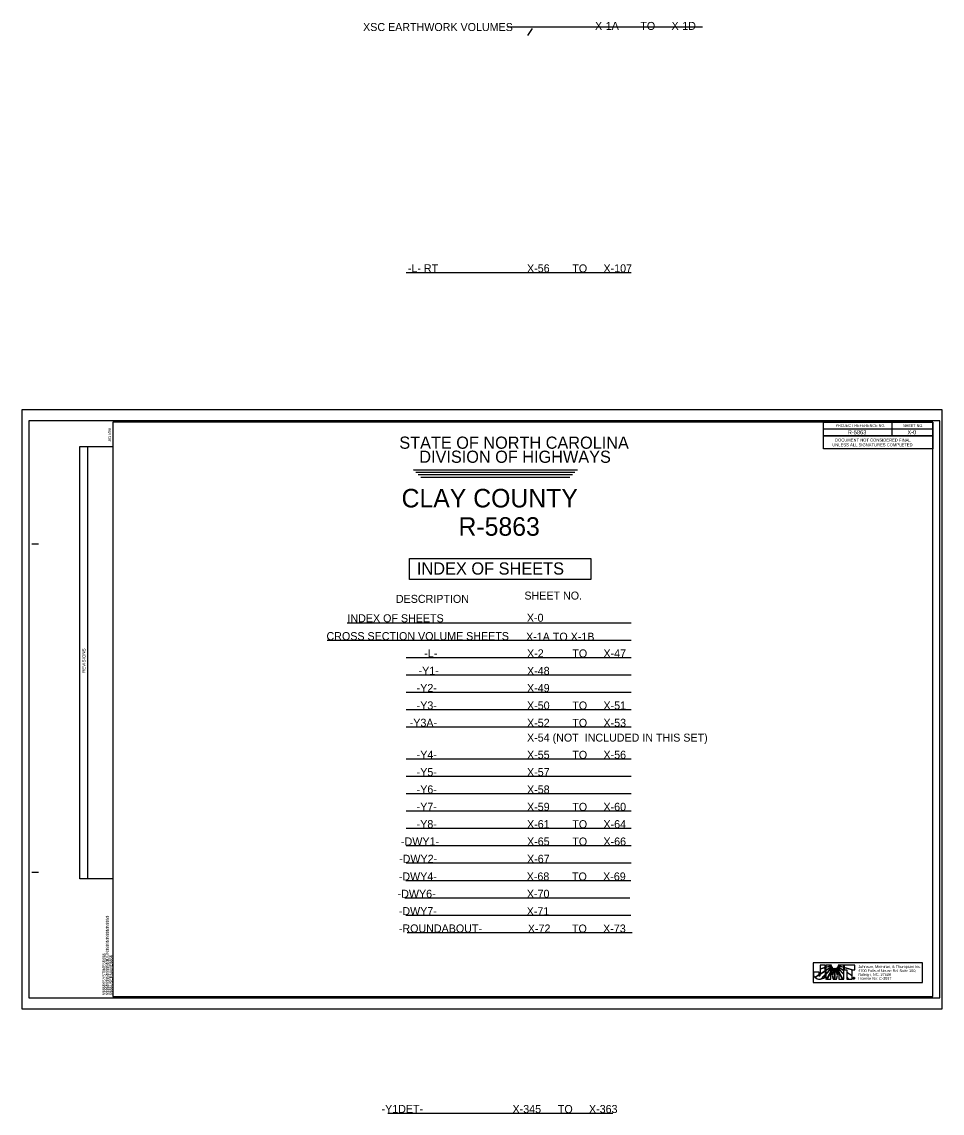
# Model space of a CAD drawing. Extents: x -1147 to 1810, y 2549 to 4545.
# Drawn here: x -1147 to 536, y 2549 to 4545 of the extents above; entities that cross this region are included whole.
import ezdxf

# ---------------------------------------------------------------- set-up
doc = ezdxf.new("R2010")
doc.units = 0
for name, color, linetype in [('Default', 7, 'Continuous'), ('Old_Level_12', 7, 'Continuous'), ('Old_Level_40', 7, 'Continuous'), ('Old_Level_44', 7, 'Continuous'), ('Prop Dimension Text', 7, 'Continuous'), ('Scratch_Level_1', 7, 'Continuous'), ('Sheet Block Revision CELL', 7, 'Continuous'), ('Sheet Cutting Line CELL', 7, 'Continuous'), ('Sheet Data Field CELL', 7, 'Continuous'), ('Sheet Plan CELL', 7, 'Continuous'), ('Sheet Plot Border Inside CELL', 7, 'Continuous'), ('Sheet Plot Border Outside CELL', 7, 'Continuous'), ('Sheet Sticker Exception Certification CELL', 7, 'Continuous')]:
    doc.layers.add(name, color=color, linetype=linetype)

msp = doc.modelspace()

# ---------------------------------------------------------------- linework, layer by layer
at = {"layer": 'Default'}
msp.add_lwpolyline([(-438.3, 3563.7), (-106.5, 3563.7), (-106.5, 3525), (-438.3, 3525)], close=True, dxfattribs=at)
at = {"layer": 'Old_Level_12'}
for p, q in [((-431.1, 3725.9), (-131, 3725.8)), ((-431.1, 3725.8), (-131, 3725.8)), ((-426.8, 3721.2), (-135.6, 3721.2)), ((-422.2, 3716.7), (-140.1, 3716.7)), ((-417.7, 3712.3), (-144.7, 3712.3))]:
    msp.add_line(p, q, dxfattribs=at)
at = {"layer": 'Prop Dimension Text'}
for p, q in [((322.3, 2819.6), (312.9, 2819.6)), ((312.9, 2819.6), (313, 2813.4)), ((313, 2813.4), (322.3, 2816)), ((322.3, 2815.3), (313, 2812.6)), ((322.3, 2816), (322.3, 2819.6)), ((322.3, 2809.9), (322.3, 2815.3)), ((333.8, 2819.6), (323.3, 2819.6)), ((323.3, 2819.6), (323.3, 2816.3)), ((323.3, 2816.3), (331.1, 2818.4)), ((331.1, 2817.7), (323.3, 2815.5)), ((323.3, 2815.5), (323.3, 2810.5)), ((323.3, 2810.5), (330.3, 2814.9)), ((331.4, 2814.8), (323.3, 2809.7)), ((323.3, 2803.8), (333.2, 2814.1)), ((333.6, 2813.6), (323.3, 2802.8)), ((330.3, 2814.9), (334.2, 2818.1)), ((331.1, 2818.4), (333.8, 2819.6)), ((334.2, 2818.1), (331.1, 2817.7)), ((335, 2816.6), (331.4, 2814.8)), ((333.2, 2814.1), (335, 2816.6)), ((336, 2815.5), (333.6, 2813.6)), ((334.9, 2812.5), (336, 2815.5)), ((337.4, 2814.7), (335.5, 2812.3)), ((337.1, 2811.8), (337.4, 2814.7)), ((338.9, 2814.3), (337.7, 2811.3)), ((339.3, 2806.9), (338.9, 2814.3)), ((340.5, 2814.3), (340, 2806.9)), ((341.7, 2811.3), (340.5, 2814.3)), ((342, 2814.7), (342.3, 2811.7)), ((343.8, 2812.3), (342, 2814.7)), ((343.3, 2815.5), (344.5, 2812.5)), ((345.8, 2813.6), (343.3, 2815.5)), ((344.4, 2816.6), (346.2, 2814.1)), ((348, 2814.8), (344.4, 2816.6)), ((345.2, 2818.1), (349.1, 2814.9)), ((348.1, 2817.7), (345.2, 2818.1)), ((356.1, 2819.6), (345.7, 2819.6)), ((345.7, 2819.6), (348.4, 2818.4)), ((356.1, 2802.8), (345.8, 2813.6)), ((346.2, 2814.1), (356.1, 2803.7)), ((356.1, 2809.7), (348, 2814.8)), ((356.1, 2815.5), (348.1, 2817.7)), ((348.4, 2818.4), (356.1, 2816.2)), ((349.1, 2814.9), (356.1, 2810.6)), ((356.1, 2816.2), (356.1, 2819.6)), ((356.1, 2810.6), (356.1, 2815.5)), ((376.5, 2819.7), (356.8, 2819.7)), ((356.8, 2819.7), (356.9, 2816)), ((356.9, 2816), (356.9, 2815.9)), ((356.9, 2815.9), (372.4, 2811.6)), ((356.9, 2815.4), (356.9, 2815.3)), ((371.4, 2811.2), (356.9, 2815.4)), ((356.9, 2815.3), (356.9, 2811.5)), ((376.5, 2811.6), (376.5, 2819.7)), ((313, 2812.6), (313, 2803.9)), ((313, 2803.9), (322.3, 2809.9)), ((323.3, 2809.7), (323.3, 2803.8)), ((323.3, 2802.8), (323.3, 2794.3)), ((323.3, 2794.3), (324.8, 2794.3)), ((324.8, 2794.3), (332.5, 2808.2)), ((332.5, 2806.8), (325.6, 2794.3)), ((325.6, 2794.3), (332.6, 2794.3)), ((332.5, 2808.2), (332.5, 2810.6)), ((332.5, 2810.6), (332.9, 2808.9)), ((332.6, 2794.3), (332.5, 2806.8)), ((332.9, 2808.9), (334.9, 2812.5)), ((335.5, 2812.3), (333.2, 2808.1)), ((333.2, 2808.1), (334.7, 2802.4)), ((334.7, 2802.4), (337.1, 2811.8)), ((337.7, 2811.3), (335, 2801.1)), ((335, 2801.1), (336.8, 2794.4)), ((336.8, 2794.4), (339.4, 2794.4)), ((339.4, 2794.4), (339.3, 2806.9)), ((340, 2806.9), (340, 2794.4)), ((340, 2794.4), (342.6, 2794.4)), ((344.4, 2801), (341.7, 2811.3)), ((342.3, 2811.7), (344.7, 2802.2)), ((342.6, 2794.4), (344.4, 2801)), ((346.2, 2807.9), (343.8, 2812.3)), ((344.5, 2812.5), (346.5, 2808.8)), ((344.7, 2802.2), (346.2, 2807.9)), ((346.5, 2808.8), (346.9, 2810.7)), ((346.9, 2810.7), (346.9, 2807.9)), ((346.9, 2807.9), (354.4, 2794.4)), ((353.7, 2794.4), (346.9, 2806.6)), ((346.9, 2806.6), (347, 2794.4)), ((347, 2794.4), (353.7, 2794.4)), ((354.4, 2794.4), (356.1, 2794.4)), ((356.1, 2803.7), (356.1, 2809.7)), ((356.1, 2794.4), (356.1, 2802.8)), ((356.9, 2811.5), (361.7, 2811.5)), ((361.7, 2811.5), (361.7, 2807.1)), ((361.7, 2807.1), (371.4, 2800.9)), ((361.7, 2806.3), (361.7, 2797.9)), ((371.4, 2800.2), (361.7, 2806.3)), ((361.7, 2797.9), (365, 2794.4)), ((364.1, 2794.4), (361.7, 2797)), ((361.7, 2797), (361.7, 2794.4)), ((361.7, 2794.4), (364.1, 2794.4)), ((365, 2794.4), (371.4, 2794.4)), ((371.4, 2800.9), (371.4, 2811.2)), ((371.4, 2794.4), (371.4, 2800.2)), ((372.4, 2811.6), (376.5, 2811.6)), ((373.8, 2795.3), (373.8, 2796.7)), ((373.8, 2796.7), (374.4, 2796.7)), ((374.2, 2795.3), (373.8, 2795.3)), ((374.4, 2796.4), (374.2, 2796.4)), ((374.2, 2796.4), (374.2, 2796.1)), ((374.2, 2796.1), (374.4, 2796.1)), ((374.4, 2795.8), (374.2, 2795.8)), ((374.2, 2795.8), (374.2, 2795.3)), ((374.4, 2797.5), (374.4, 2797.2)), ((374.4, 2797.2), (374.4, 2797.5)), ((374.4, 2796.7), (374.4, 2796.4)), ((374.4, 2796.4), (374.4, 2796.7)), ((374.4, 2796.7), (374.5, 2796.7)), ((374.5, 2796.4), (374.4, 2796.4)), ((374.4, 2796.1), (374.4, 2795.8)), ((374.4, 2795.8), (374.4, 2796.1)), ((374.4, 2796.1), (374.4, 2796.1)), ((374.4, 2795.8), (374.4, 2795.8)), ((374.4, 2794.7), (374.4, 2794.4)), ((374.4, 2794.4), (374.4, 2794.7)), ((374.4, 2794.7), (374.4, 2794.7)), ((374.4, 2794.4), (374.4, 2794.4))]:
    msp.add_line(p, q, dxfattribs=at)
msp.add_lwpolyline([(300.3, 2787.9), (500.3, 2787.9), (500.3, 2824), (300.3, 2824)], close=True, dxfattribs=at)
for points in [[(313, 2813.4), (322.3, 2816), (322.3, 2819.6), (312.9, 2819.6), (313, 2813.4)], [(313, 2803.9), (322.3, 2809.9), (322.3, 2815.3), (313, 2812.6), (313, 2803.9)], [(331.1, 2818.4), (333.8, 2819.6), (323.3, 2819.6), (323.3, 2816.3), (331.1, 2818.4)], [(323.3, 2815.5), (323.3, 2810.5), (330.3, 2814.9), (334.2, 2818.1), (331.1, 2817.7), (323.3, 2815.5)], [(323.3, 2809.7), (323.3, 2803.8), (333.2, 2814.1), (335, 2816.6), (331.4, 2814.8), (323.3, 2809.7)], [(336, 2815.5), (333.6, 2813.6), (323.3, 2802.8), (323.3, 2794.3), (324.8, 2794.3), (332.5, 2808.2), (332.5, 2810.6), (332.9, 2808.9), (334.9, 2812.5), (336, 2815.5)], [(337.4, 2814.7), (335.5, 2812.3), (333.2, 2808.1), (334.7, 2802.4), (337.1, 2811.8), (337.4, 2814.7)], [(337.7, 2811.3), (335, 2801.1), (336.8, 2794.4), (339.4, 2794.4), (339.3, 2806.9), (338.9, 2814.3), (337.7, 2811.3)], [(340.5, 2814.3), (340, 2806.9), (340, 2794.4), (342.6, 2794.4), (344.4, 2801), (341.7, 2811.3), (340.5, 2814.3)], [(342, 2814.7), (342.3, 2811.7), (344.7, 2802.2), (346.2, 2807.9), (343.8, 2812.3), (342, 2814.7)], [(343.3, 2815.5), (344.5, 2812.5), (346.5, 2808.8), (346.9, 2810.7), (346.9, 2807.9), (354.4, 2794.4), (356.1, 2794.4), (356.1, 2802.8), (345.8, 2813.6), (343.3, 2815.5)], [(344.4, 2816.6), (346.2, 2814.1), (356.1, 2803.7), (356.1, 2809.7), (348, 2814.8), (344.4, 2816.6)], [(345.2, 2818.1), (349.1, 2814.9), (356.1, 2810.6), (356.1, 2815.5), (348.1, 2817.7), (345.2, 2818.1)], [(348.4, 2818.4), (356.1, 2816.2), (356.1, 2819.6), (345.7, 2819.6), (348.4, 2818.4)], [(376.5, 2819.7), (356.8, 2819.7), (356.9, 2816), (356.9, 2815.9), (372.4, 2811.6), (376.5, 2811.6), (376.5, 2819.7)], [(356.9, 2815.4), (356.9, 2815.3), (356.9, 2811.5), (361.7, 2811.5), (361.7, 2807.1), (371.4, 2800.9), (371.4, 2811.2), (356.9, 2815.4)], [(325.6, 2794.3), (332.6, 2794.3), (332.5, 2806.8), (325.6, 2794.3)], [(347, 2794.4), (353.7, 2794.4), (346.9, 2806.6), (347, 2794.4)], [(361.7, 2806.3), (361.7, 2797.9), (365, 2794.4), (371.4, 2794.4), (371.4, 2800.2), (361.7, 2806.3), (361.7, 2806.3)], [(361.7, 2794.4), (361.7, 2794.4), (364.1, 2794.4), (361.7, 2797), (361.7, 2794.4)], [(375.1, 2795.6), (375.1, 2795.5), (375.1, 2795.5), (375.1, 2795.4), (375.1, 2795.3), (374.8, 2795.3)]]:
    msp.add_lwpolyline(points, dxfattribs=at)
for points, degree in [([(310.3, 2807.9), (310.3, 2807.9), (301.6, 2807.9), (301.6, 2807.9), (301.6, 2807.9), (301.6, 2802.5), (301.6, 2802.5), (301.6, 2802.5), (301.6, 2801.9), (301.6, 2801.9), (301.6, 2800.2), (302.2, 2798.9), (303.2, 2797.8), (303.2, 2797.8), (310.3, 2802.1), (310.3, 2802.2), (310.3, 2802.2), (310.3, 2807.9), (310.3, 2807.9)], 3), ([(311.6, 2800.1), (311.1, 2800.1), (310.6, 2800.4), (310.4, 2801.5), (310.4, 2801.5), (303.7, 2797.3), (303.7, 2797.3), (305.7, 2795.1), (309, 2793.8), (311.8, 2793.8), (312.6, 2793.8), (313.1, 2793.9), (313.9, 2794.1), (313.9, 2794.1), (322.3, 2802.8), (322.3, 2802.8), (322.3, 2802.8), (322.3, 2809.1), (322.3, 2809.1), (322.3, 2809.1), (313, 2803.1), (313, 2803.1), (313, 2800.8), (312.4, 2800.1), (311.6, 2800.1)], 3), ([(311.6, 2800.1), (311.1, 2800.1), (310.6, 2800.4), (310.4, 2801.5), (310.4, 2801.5), (303.7, 2797.3), (303.7, 2797.3), (305.7, 2795.1), (309, 2793.8), (311.8, 2793.8), (312.6, 2793.8), (313.1, 2793.9), (313.9, 2794.1), (313.9, 2794.1), (322.3, 2802.8), (322.3, 2802.8), (322.3, 2802.8), (322.3, 2809.1), (322.3, 2809.1), (322.3, 2809.1), (313, 2803.1), (313, 2803.1), (313, 2800.8), (312.4, 2800.1), (311.6, 2800.1)], 3), ([(322.3, 2801.8), (322.3, 2801.8), (315, 2794.3), (315, 2794.3), (318.6, 2795.1), (322.2, 2797.5), (322.3, 2801.8)], 3), ([(374.4, 2794.4), (374, 2794.4), (373.6, 2794.5), (373.3, 2794.9), (373, 2795.2), (372.8, 2795.5), (372.8, 2796), (372.8, 2796.4), (373, 2796.8), (373.3, 2797.1), (373.6, 2797.4), (374, 2797.5), (374.4, 2797.5)], 3), ([(374.4, 2797.2), (374.1, 2797.2), (373.8, 2797.1), (373.5, 2796.9), (373.3, 2796.6), (373.2, 2796.3), (373.2, 2796), (373.2, 2795.6), (373.3, 2795.3), (373.5, 2795.1), (373.8, 2794.8), (374.1, 2794.7), (374.4, 2794.7)], 3), ([(374.4, 2797.5), (374.9, 2797.5), (375.2, 2797.4), (375.6, 2797.1), (375.9, 2796.8), (376, 2796.4), (376, 2796)], 3), ([(374.4, 2794.7), (374.8, 2794.7), (375.1, 2794.8), (375.3, 2795.1), (375.6, 2795.3), (375.7, 2795.6), (375.7, 2796), (375.7, 2796.3), (375.6, 2796.6), (375.3, 2796.9), (375.1, 2797.1), (374.8, 2797.2), (374.4, 2797.2)], 3), ([(374.4, 2796.1), (374.6, 2796.1), (374.8, 2796.1), (374.8, 2796.3), (374.8, 2796.4), (374.7, 2796.4), (374.5, 2796.4)], 3), ([(376, 2796), (376, 2795.5), (375.9, 2795.2), (375.6, 2794.8), (375.3, 2794.5), (374.9, 2794.4), (374.4, 2794.4)], 3), ([(374.7, 2795.8), (374.6, 2795.8), (374.6, 2795.8), (374.4, 2795.8)], 2), ([(374.5, 2796.7), (374.9, 2796.7), (375.1, 2796.6), (375.1, 2796.3), (375.1, 2796.1), (375, 2796), (374.9, 2796)], 3), ([(374.8, 2795.3), (374.8, 2795.3), (374.7, 2795.4), (374.7, 2795.5), (374.7, 2795.7), (374.7, 2795.7), (374.7, 2795.8)], 3), ([(374.9, 2796), (375, 2795.9), (375, 2795.8), (375.1, 2795.6)], 2)]:
    msp.add_open_spline(points, degree=degree, dxfattribs=at)
at = {"layer": 'Scratch_Level_1'}
for p, q in [((-259, 4535.2), (-220.9, 4535.2)), ((-259, 4535.2), (97.9, 4535.2)), ((-222, 4519.9), (-213.3, 4532.3)), ((-444.1, 4086.5), (-32.7, 4086.5)), ((-552.1, 3445.8), (-32.7, 3445.8)), ((-588.7, 3414.1), (-32.7, 3414.1)), ((-444.1, 3382.4), (-32.7, 3382.4)), ((-444.1, 3350.7), (-32.7, 3350.7)), ((-444.1, 3319), (-32.7, 3319)), ((-444.1, 3287.3), (-32.7, 3287.3)), ((-444.1, 3255.6), (-32.7, 3255.6)), ((-444.1, 3197.1), (-32.7, 3197.1)), ((-444.1, 3165.4), (-32.7, 3165.4)), ((-444.1, 3133.7), (-32.7, 3133.7)), ((-444.1, 3102), (-32.7, 3102)), ((-444.1, 3070.3), (-32.7, 3070.3)), ((-444.1, 3038.6), (-32.7, 3038.6)), ((-444.1, 3006.9), (-32.7, 3006.9)), ((-444.7, 2974.6), (-33.3, 2974.6)), ((-446.8, 2942.9), (-35.3, 2942.9)), ((-444.7, 2911.2), (-33.3, 2911.2)), ((-442.6, 2879.5), (-31.2, 2879.5)), ((-477.7, 2549.4), (-66.2, 2549.4))]:
    msp.add_line(p, q, dxfattribs=at)
at = {"layer": 'Sheet Block Revision CELL'}
msp.add_line((-1026.8, 2977.7), (-1026.8, 3768.4), dxfattribs=at)
msp.add_lwpolyline([(-1041.4, 2977.7), (-1041.4, 3768.3), (-980.8, 3768.4), (-980.8, 2977.7)], close=True, dxfattribs=at)
at = {"layer": 'Sheet Cutting Line CELL'}
for p, q in [((536.2, 3835.2), (-1147.3, 3835.2)), ((-1147.3, 3835.2), (-1147.3, 2740.2)), ((-1147.3, 2740.2), (536.2, 2740.2))]:
    msp.add_line(p, q, dxfattribs=at)
at = {"layer": 'Sheet Plan CELL'}
for p, q in [((-980.8, 3812.7), (-980.8, 3812.7)), ((444.1, 3812.7), (444.2, 3787.7)), ((319.1, 3800.2), (519.2, 3800.2)), ((319.1, 3787.6), (519.2, 3787.7)), ((319.1, 3787.6), (519.2, 3787.7)), ((-1129.3, 3590.2), (-1116.8, 3590.2)), ((-1129.3, 2990.2), (-1116.8, 2990.2)), ((-980.8, 2762.7), (-980.8, 2762.7))]:
    msp.add_line(p, q, dxfattribs=at)
for points in [[(519.2, 3812.7), (-980.8, 3812.7), (-980.8, 2762.7), (519.2, 2762.7)], [(319.1, 3812.7), (519.2, 3812.7), (519.2, 3787.7), (319.1, 3787.6)]]:
    msp.add_lwpolyline(points, close=True, dxfattribs=at)
at = {"layer": 'Sheet Plot Border Inside CELL'}
msp.add_lwpolyline([(-1134.3, 2760.2), (531.7, 2760.2), (531.7, 3815.2), (-1134.3, 3815.2)], close=True, dxfattribs=at)
at = {"layer": 'Sheet Plot Border Outside CELL'}
msp.add_lwpolyline([(-1147.3, 2740.2), (536.2, 2740.2), (536.2, 3835.2), (-1147.3, 3835.2)], close=True, dxfattribs=at)
at = {"layer": 'Sheet Sticker Exception Certification CELL'}
for p, q in [((319.1, 3764.1), (319.1, 3787.6)), ((319.1, 3787.6), (519.2, 3787.6)), ((519.2, 3787.6), (519.2, 3764.1)), ((519.2, 3764.1), (319.1, 3764.1))]:
    msp.add_line(p, q, dxfattribs=at)

# ---------------------------------------------------------------- texts
at = {"layer": 'Default'}
for s, p in [('XSC EARTHWORK VOLUMES ', (-523.1, 4527.8)), ('X-1A', (-98.8, 4529.9)), ('TO', (-15.9, 4529.8)), ('X-1D', (41.1, 4529.9)), ('-L- RT', (-441.2, 4086.7)), ('X-56', (-223.2, 4086.6)), ('TO', (-140.4, 4086.5)), ('X-107', (-83.4, 4086.6)), ('INDEX OF SHEETS ', (-551.7, 3446.8)), ('X-0', (-223.5, 3447.7)), ('CROSS SECTION VOLUME SHEETS', (-590, 3414.2)), ('X-1A TO X-1B', (-224.9, 3413.2)), ('-L- ', (-411.2, 3382.8)), ('X-2', (-223.2, 3382.7)), ('TO', (-140.4, 3382.6)), ('X-47', (-83.4, 3382.7)), ('-Y1-', (-421.6, 3350.8)), ('X-48', (-223.2, 3350.7)), ('-Y2- ', (-425.1, 3319.3)), ('X-49', (-223.2, 3319.3)), ('-Y3-', (-425.1, 3287.5)), ('X-50', (-223.2, 3287.4)), ('TO', (-140.4, 3287.3)), ('X-51', (-83.4, 3287.4)), ('-Y3A-', (-437.8, 3255.8)), ('X-52', (-223.2, 3255.7)), ('TO', (-140.4, 3255.6)), ('X-53', (-83.4, 3255.7)), ('X-54 (NOT  INCLUDED IN THIS SET)', (-223.2, 3228.6)), ('-Y4-', (-425.1, 3197.3)), ('X-55', (-223.2, 3197.3)), ('TO', (-140.4, 3197.2)), ('X-56', (-83.4, 3197.3)), ('-Y5-', (-425.1, 3165.6)), ('X-57', (-223.2, 3165.6)), ('-Y6-', (-425.1, 3133.9)), ('X-58', (-223.2, 3133.8)), ('-Y7-', (-425.1, 3102.2)), ('X-59', (-223.2, 3102.1)), ('TO', (-140.4, 3102)), ('X-60', (-83.4, 3102.1)), ('-Y8-', (-425.1, 3070.5)), ('X-61', (-223.2, 3070.4)), ('TO', (-140.4, 3070.3)), ('X-64', (-83.4, 3070.4)), ('-DWY1-', (-453.7, 3038.8)), ('X-65', (-223.2, 3038.7)), ('TO', (-140.4, 3038.6)), ('X-66', (-83.4, 3038.7)), ('-DWY2-', (-457.2, 3007.1)), ('X-67', (-223.2, 3007)), ('-DWY4-', (-457.8, 2974.8)), ('X-68', (-223.8, 2974.8)), ('TO', (-141, 2974.7)), ('X-69', (-84, 2974.8)), ('-DWY6-', (-459.9, 2943.1)), ('X-70', (-223.5, 2943.1)), ('-DWY7-', (-457.8, 2911.4)), ('X-71', (-223.8, 2911.3)), ('-ROUNDABOUT-', (-457.7, 2879.7)), ('X-72', (-221.7, 2879.6)), ('TO', (-141, 2879.5)), ('X-73', (-84, 2879.6)), ('-Y1DET-', (-489.3, 2549.7)), ('X-345', (-249.7, 2549.6)), ('TO', (-166.8, 2549.5)), ('X-363', (-109.9, 2549.6))]:
    msp.add_text(s, height=14.63, dxfattribs=at).set_placement(p)
for s, height, p in [('INDEX OF SHEETS', 22.358, (-424.7, 3534)), ('DESCRIPTION', 14.63, (-463.1, 3482.3)), ('SHEET NO.', 14.63, (-228, 3488.3))]:
    msp.add_text(s, height=height, rotation=359.992, dxfattribs=at).set_placement(p)
at = {"layer": 'Old_Level_40'}
for s, height, p in [('CLAY COUNTY', 33.906, (-452.7, 3656.8)), ('R-5863', 33.91, (-348.6, 3605))]:
    msp.add_text(s, height=height, rotation=359.9982, dxfattribs=at).set_placement(p)
at = {"layer": 'Old_Level_44'}
for s, p in [('STATE OF NORTH CAROLINA', (-456.8, 3764.1)), ('DIVISION OF HIGHWAYS', (-420.3, 3738.4))]:
    msp.add_text(s, height=22.246, rotation=359.9915, dxfattribs=at).set_placement(p)
at = {"layer": 'Prop Dimension Text'}
for s, height, p in [('Johnson, Mirmiran, & Thompson Inc.', 5.111, (382.7, 2814.7)), ('4700 Falls of Neuse Rd, Suite 100, ', 4.965, (382.7, 2807.2)), ('Raleigh, NC, 27609', 4.965, (382.7, 2800.2)), ('License No: C-3097', 4.965, (382.7, 2793.1))]:
    msp.add_text(s, height=height, dxfattribs=at).set_placement(p)
msp.add_text('www.jmt.com', height=1.241, rotation=270, dxfattribs=at).set_placement((340.6, 2805.6))
at = {"layer": 'Sheet Block Revision CELL'}
msp.add_text('REVISIONS', height=6, rotation=90, dxfattribs=at).set_placement((-1030.9, 3353.9))
at = {"layer": 'Sheet Data Field CELL'}
for s, p in [('R-5863', (363.5, 3790.4)), ('X-0', (472.6, 3790.5))]:
    msp.add_text(s, height=7.5, rotation=0, dxfattribs=at).set_placement(p)
at = {"layer": 'Sheet Plan CELL'}
for s, height, rotation, p in [('8/17/99', 5.25, 90, (-984.1, 3777.5)), ('PROJECT REFERENCE NO.', 5, 0, (341.3, 3804)), ('SHEET NO.', 5, 0, (464.5, 3803.9)), ('$$$$$$$$$$$$$$$$DGN$$$$$$$$$$$$$$$$', 5.25, 90, (-988.5, 2765.1)), ('$$$$$$SYSTIME$$$$$', 5.25, 90, (-994.6, 2765.1)), ('$$$$USERNAME$$$$', 5.25, 90, (-981.9, 2765.1))]:
    msp.add_text(s, height=height, rotation=rotation, dxfattribs=at).set_placement(p)
at = {"layer": 'Sheet Sticker Exception Certification CELL'}
for s, p in [('UNLESS ALL SIGNATURES COMPLETED', (335.1, 3768.5)), ('DOCUMENT NOT CONSIDERED FINAL', (340.2, 3777.3))]:
    msp.add_text(s, height=5.5, dxfattribs=at).set_placement(p)

doc.saveas('drawing.dxf')
